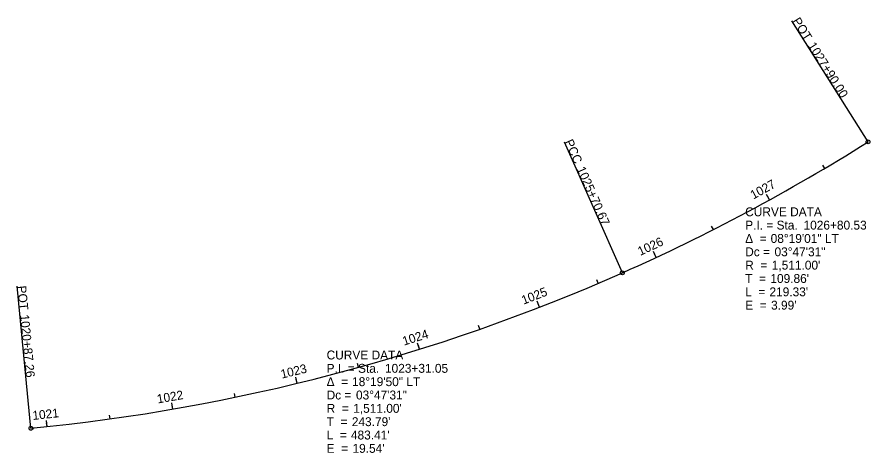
# Model space of a CAD drawing. Extents: x 2197084 to 2197755, y 661730 to 662073.
import ezdxf

# ---------------------------------------------------------------- set-up
doc = ezdxf.new("R2010")
doc.units = 0
for name, color, linetype in [('GE_P_Alignment', 7, 'Continuous'), ('GE_P_Alignment_1000_Curve_Data', 7, 'Continuous'), ('GE_P_Alignment_1000_Stations', 7, 'Continuous'), ('GE_P_Alignment_100_Curve_Data', 7, 'Continuous'), ('GE_P_Alignment_100_Stations', 7, 'Continuous'), ('GE_P_Alignment_500_Curve_Data', 7, 'Continuous'), ('GE_P_Alignment_500_Stations', 7, 'Continuous')]:
    doc.layers.add(name, color=color, linetype=linetype)

msp = doc.modelspace()

# ---------------------------------------------------------------- linework, layer by layer
at = {"layer": 'GE_P_Alignment'}
for start, end in [(293.89376, 302.21069), (275.56332, 293.89376)]:
    msp.add_arc((2196948.19, 663252.84), 1511, start, end, dxfattribs=at)
at = {"layer": 'GE_P_Alignment_1000_Stations'}
for p, q in [((2197753.6, 661974.4), (2197693.64, 662069.58)), ((2197560.21, 661871.34), (2197514.64, 661974.2)), ((2197094.68, 661748.96), (2197083.77, 661860.93)), ((2197494.95, 661844.24), (2197493.86, 661847.03))]:
    msp.add_line(p, q, dxfattribs=at)
for centre in [(2197753.6, 661974.4), (2197560.21, 661871.34), (2197094.68, 661748.96)]:
    msp.add_circle(centre, 1.5, dxfattribs=at)
at = {"layer": 'GE_P_Alignment_100_Stations'}
for p, q in [((2197753.6, 661974.4), (2197693.64, 662069.58)), ((2197560.21, 661871.34), (2197514.64, 661974.2)), ((2197719.48, 661953.53), (2197717.95, 661956.1)), ((2197676.07, 661928.72), (2197673.66, 661933.1)), ((2197631.86, 661905.36), (2197630.51, 661908.04)), ((2197586.91, 661883.48), (2197584.8, 661888.01)), ((2197541.25, 661863.1), (2197540.08, 661865.86)), ((2197094.68, 661748.96), (2197083.77, 661860.93)), ((2197494.95, 661844.24), (2197493.14, 661848.9)), ((2197448.05, 661826.92), (2197447.06, 661829.75)), ((2197400.6, 661811.16), (2197399.1, 661815.93)), ((2197352.65, 661796.98), (2197351.85, 661799.87)), ((2197304.26, 661784.4), (2197303.09, 661789.26)), ((2197255.49, 661773.42), (2197254.88, 661776.36)), ((2197206.37, 661764.07), (2197205.52, 661768.99)), ((2197156.98, 661756.34), (2197156.56, 661759.31)), ((2197107.35, 661750.25), (2197106.82, 661755.22))]:
    msp.add_line(p, q, dxfattribs=at)
for centre in [(2197753.6, 661974.4), (2197560.21, 661871.34), (2197094.68, 661748.96)]:
    msp.add_circle(centre, 1.5, dxfattribs=at)
at = {"layer": 'GE_P_Alignment_500_Stations'}
for p, q in [((2197753.6, 661974.4), (2197693.64, 662069.58)), ((2197560.21, 661871.34), (2197514.64, 661974.2)), ((2197676.07, 661928.72), (2197674.63, 661931.35)), ((2197586.91, 661883.48), (2197585.64, 661886.2)), ((2197094.68, 661748.96), (2197083.77, 661860.93)), ((2197494.95, 661844.24), (2197493.14, 661848.9)), ((2197400.6, 661811.16), (2197399.7, 661814.02)), ((2197304.26, 661784.4), (2197303.56, 661787.31)), ((2197206.37, 661764.07), (2197205.86, 661767.02)), ((2197107.35, 661750.25), (2197107.03, 661753.23))]:
    msp.add_line(p, q, dxfattribs=at)
for centre in [(2197753.6, 661974.4), (2197560.21, 661871.34), (2197094.68, 661748.96)]:
    msp.add_circle(centre, 1.5, dxfattribs=at)

# ---------------------------------------------------------------- texts
at = {"layer": 'GE_P_Alignment_1000_Curve_Data'}
for s, p in [('CURVE DATA', (2197656.91, 661915.87)), ('P.I. = Sta. ', (2197656.91, 661905.37)), ('1026+80.53', (2197702.83, 661905.37)), ('Δ  = ', (2197656.91, 661894.87)), ('08°19\'01" LT', (2197676.96, 661894.87)), ('Dc = ', (2197656.91, 661884.37)), ('03°47\'31"', (2197680, 661884.37)), ('R  = ', (2197656.91, 661873.87)), ("1,511.00'", (2197677.83, 661873.87)), ('T  = ', (2197656.91, 661863.37)), ("109.86'", (2197676.74, 661863.37)), ('L  = ', (2197656.91, 661852.87)), ("219.33'", (2197676.02, 661852.87)), ('E  = ', (2197656.91, 661842.37)), ("3.99'", (2197677.29, 661842.37)), ('CURVE DATA', (2197327.44, 661803.15)), ('P.I. = Sta. ', (2197327.44, 661792.65)), ('1023+31.05', (2197373.36, 661792.65)), ('Δ  = ', (2197327.44, 661782.15)), ('18°19\'50" LT', (2197347.5, 661782.15)), ('Dc = ', (2197327.44, 661771.65)), ('03°47\'31"', (2197350.54, 661771.65)), ('R  = ', (2197327.44, 661761.15)), ("1,511.00'", (2197348.36, 661761.15)), ('T  = ', (2197327.44, 661750.65)), ("243.79'", (2197347.27, 661750.65)), ('L  = ', (2197327.44, 661740.15)), ("483.41'", (2197346.56, 661740.15)), ('E  = ', (2197327.44, 661729.65)), ("19.54'", (2197347.82, 661729.65))]:
    msp.add_text(s, height=7, dxfattribs=at).set_placement(p)
at = {"layer": 'GE_P_Alignment_1000_Stations'}
for s, rotation, p in [('POT', 302.21069, (2197693.78, 662069.58)), ('1027+90.00', 302.21069, (2197705.95, 662050.26)), ('PCC', 293.89376, (2197514.61, 661974.55)), ('1025+70.67', 293.89376, (2197524.08, 661953.19)), ('POT', 275.56332, (2197083.89, 661860.87)), ('1020+87.26', 275.56332, (2197086.11, 661838.15))]:
    msp.add_text(s, height=7, rotation=rotation, dxfattribs=at).set_placement(p)
at = {"layer": 'GE_P_Alignment_100_Curve_Data'}
for s, p in [('CURVE DATA', (2197656.91, 661915.87)), ('P.I. = Sta. ', (2197656.91, 661905.37)), ('1026+80.53', (2197702.83, 661905.37)), ('Δ  = ', (2197656.91, 661894.87)), ('08°19\'01" LT', (2197676.96, 661894.87)), ('Dc = ', (2197656.91, 661884.37)), ('03°47\'31"', (2197680, 661884.37)), ('R  = ', (2197656.91, 661873.87)), ("1,511.00'", (2197677.83, 661873.87)), ('T  = ', (2197656.91, 661863.37)), ("109.86'", (2197676.74, 661863.37)), ('L  = ', (2197656.91, 661852.87)), ("219.33'", (2197676.02, 661852.87)), ('E  = ', (2197656.91, 661842.37)), ("3.99'", (2197677.29, 661842.37)), ('CURVE DATA', (2197327.44, 661803.15)), ('P.I. = Sta. ', (2197327.44, 661792.65)), ('1023+31.05', (2197373.36, 661792.65)), ('Δ  = ', (2197327.44, 661782.15)), ('18°19\'50" LT', (2197347.5, 661782.15)), ('Dc = ', (2197327.44, 661771.65)), ('03°47\'31"', (2197350.54, 661771.65)), ('R  = ', (2197327.44, 661761.15)), ("1,511.00'", (2197348.36, 661761.15)), ('T  = ', (2197327.44, 661750.65)), ("243.79'", (2197347.27, 661750.65)), ('L  = ', (2197327.44, 661740.15)), ("483.41'", (2197346.56, 661740.15)), ('E  = ', (2197327.44, 661729.65)), ("19.54'", (2197347.82, 661729.65))]:
    msp.add_text(s, height=7, dxfattribs=at).set_placement(p)
at = {"layer": 'GE_P_Alignment_100_Stations'}
for s, rotation, p in [('POT', 302.21069, (2197693.78, 662069.58)), ('1027+90.00', 302.21069, (2197705.95, 662050.26)), ('PCC', 293.89376, (2197514.61, 661974.55)), ('1025+70.67', 293.89376, (2197524.08, 661953.19)), ('1027', 28.79788, (2197663.31, 661928.97)), ('1026', 25.00596, (2197574.31, 661884.63)), ('POT', 275.56332, (2197083.89, 661860.87)), ('1025', 21.21405, (2197482.44, 661846.21)), ('1020+87.26', 275.56332, (2197086.11, 661838.15)), ('1024', 17.42214, (2197388.37, 661814)), ('1023', 13.63023, (2197292.19, 661788.02)), ('1022', 9.83832, (2197194.54, 661768.48)), ('1021', 6.04641, (2197096.24, 661755.48))]:
    msp.add_text(s, height=7, rotation=rotation, dxfattribs=at).set_placement(p)
at = {"layer": 'GE_P_Alignment_500_Curve_Data'}
for s, p in [('CURVE DATA', (2197656.91, 661915.87)), ('P.I. = Sta. ', (2197656.91, 661905.37)), ('1026+80.53', (2197702.83, 661905.37)), ('Δ  = ', (2197656.91, 661894.87)), ('08°19\'01" LT', (2197676.96, 661894.87)), ('Dc = ', (2197656.91, 661884.37)), ('03°47\'31"', (2197680, 661884.37)), ('R  = ', (2197656.91, 661873.87)), ("1,511.00'", (2197677.83, 661873.87)), ('T  = ', (2197656.91, 661863.37)), ("109.86'", (2197676.74, 661863.37)), ('L  = ', (2197656.91, 661852.87)), ("219.33'", (2197676.02, 661852.87)), ('E  = ', (2197656.91, 661842.37)), ("3.99'", (2197677.29, 661842.37)), ('CURVE DATA', (2197327.44, 661803.15)), ('P.I. = Sta. ', (2197327.44, 661792.65)), ('1023+31.05', (2197373.36, 661792.65)), ('Δ  = ', (2197327.44, 661782.15)), ('18°19\'50" LT', (2197347.5, 661782.15)), ('Dc = ', (2197327.44, 661771.65)), ('03°47\'31"', (2197350.54, 661771.65)), ('R  = ', (2197327.44, 661761.15)), ("1,511.00'", (2197348.36, 661761.15)), ('T  = ', (2197327.44, 661750.65)), ("243.79'", (2197347.27, 661750.65)), ('L  = ', (2197327.44, 661740.15)), ("483.41'", (2197346.56, 661740.15)), ('E  = ', (2197327.44, 661729.65)), ("19.54'", (2197347.82, 661729.65))]:
    msp.add_text(s, height=7, dxfattribs=at).set_placement(p)
at = {"layer": 'GE_P_Alignment_500_Stations'}
for s, rotation, p in [('POT', 302.21069, (2197693.78, 662069.58)), ('1027+90.00', 302.21069, (2197705.95, 662050.26)), ('PCC', 293.89376, (2197514.61, 661974.55)), ('1025+70.67', 293.89376, (2197524.08, 661953.19)), ('POT', 275.56332, (2197083.89, 661860.87)), ('1025', 21.21405, (2197482.44, 661846.21)), ('1020+87.26', 275.56332, (2197086.11, 661838.15))]:
    msp.add_text(s, height=7, rotation=rotation, dxfattribs=at).set_placement(p)

doc.saveas('drawing.dxf')
